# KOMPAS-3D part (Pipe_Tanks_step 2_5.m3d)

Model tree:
1. X Axis
2. Y Axis
3. Z Axis  (labels: Pipe Dn 50; T-Bend Dn 50)
     Òîëùèíà ñòåíêè 1 = 1

Referenced files in C:\Documents and Settings\kashirsky\Мои документы\Camtasia Studio\Pipelines3D\Tanks\: Tanks_step 2.a3d
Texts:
  Pipe Dn 50
  Steel ASTM A295
  Three Point Plane
  Plane at Angle
  Line and Point Plane
  Axis through Two Vertices
  Axis of Feature
  Axis of Conical Surface
  Axis through Edge
  Trim by Surface
  Trim by Sketch
  Feature with No History
  Intersection Axis of Two Planes
  Two Line Plane
  Line and Face Plane
  Bend by line
  Hole in sheet body
  Cut in sheet body
  Point in CM
  Linear Dimension from Line to Point
  Surface Finish Symbol
  Geometric Tolerance Symbol
  Leader #1
  Leader #2
  Leader #3
  Shape Deviations and Datum
  Node point number
  Mark of coordination axis
  Node point designation
  Mark/Reference designation with leader
  Mark/reference designation on line
  Mark/Reference designation without leader
  T-Bend Dn 50
  Plane of section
